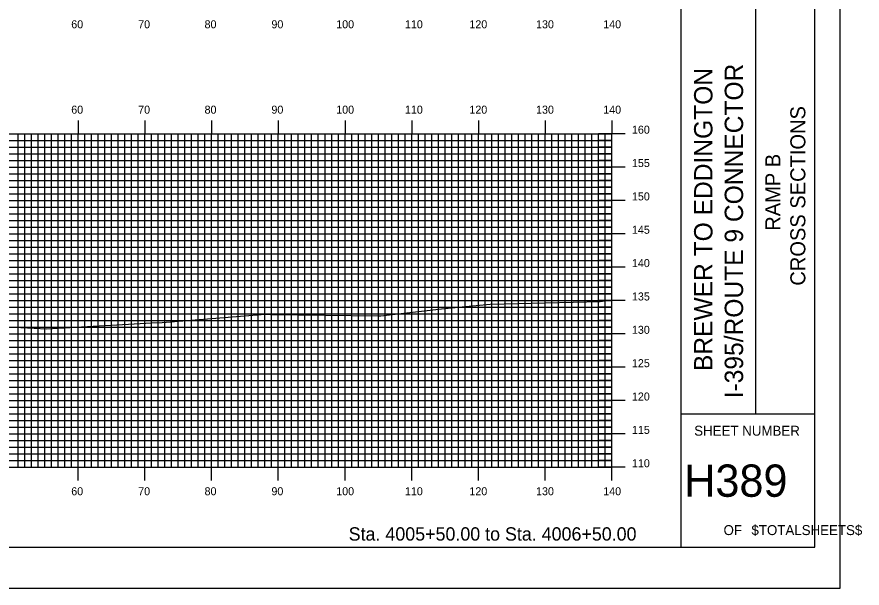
# Model space of a CAD drawing. Extents: x 851360 to 851703, y 364661 to 364881.
# Drawn here: x 851576.6 to 851703.2, y 364661.3 to 364746.9 of the extents above; entities that cross this region are included whole.
import ezdxf

# ---------------------------------------------------------------- set-up
doc = ezdxf.new("R2010")
doc.units = 0
for name, color, linetype in [('BORDER', 7, 'Continuous'), ('H_V ANNOTATION', 7, 'Continuous'), ('MAJOR', 7, 'Continuous'), ('MINOR', 7, 'Continuous'), ('PLOT BOUNDARY', 7, 'Continuous'), ('S_Roadway_Centerline', 7, 'Continuous')]:
    doc.layers.add(name, color=color, linetype=linetype)

msp = doc.modelspace()

# ---------------------------------------------------------------- linework, layer by layer
at = {"layer": 'BORDER'}
for p, q in [((851676.13, 364667.37), (851676.13, 364877.37)), ((851687.31, 364687.38), (851687.31, 364757.38)), ((851676.13, 364687.38), (851696.13, 364687.38))]:
    msp.add_line(p, q, dxfattribs=at)
msp.add_lwpolyline([(851376.13, 364667.37), (851696.13, 364667.37), (851696.13, 364877.37), (851376.13, 364877.37)], close=True, dxfattribs=at)
at = {"layer": 'MAJOR'}
for p, q in [((851585.73, 364731.37), (851585.73, 364729.37)), ((851595.73, 364731.37), (851595.73, 364729.37)), ((851605.73, 364731.37), (851605.73, 364729.37)), ((851615.73, 364731.37), (851615.73, 364729.37)), ((851625.73, 364731.37), (851625.73, 364729.37)), ((851635.73, 364731.37), (851635.73, 364729.37)), ((851645.73, 364731.37), (851645.73, 364729.37)), ((851655.73, 364731.37), (851655.73, 364729.37)), ((851665.73, 364731.37), (851665.73, 364729.37)), ((851385.73, 364729.37), (851665.73, 364729.37)), ((851385.73, 364729.37), (851665.73, 364729.37)), ((851585.73, 364679.37), (851585.73, 364729.37)), ((851595.73, 364679.37), (851595.73, 364729.37)), ((851605.73, 364679.37), (851605.73, 364729.37)), ((851615.73, 364679.37), (851615.73, 364729.37)), ((851625.73, 364679.37), (851625.73, 364729.37)), ((851635.73, 364679.37), (851635.73, 364729.37)), ((851645.73, 364679.37), (851645.73, 364729.37)), ((851655.73, 364679.37), (851655.73, 364729.37)), ((851667.73, 364729.37), (851663.72, 364729.37)), ((851665.73, 364679.37), (851665.73, 364729.37)), ((851665.73, 364679.37), (851665.73, 364729.37)), ((851385.73, 364724.37), (851665.73, 364724.37)), ((851667.73, 364724.37), (851663.72, 364724.37)), ((851385.73, 364719.37), (851665.73, 364719.37)), ((851667.73, 364719.37), (851663.72, 364719.37)), ((851385.73, 364714.37), (851665.73, 364714.37)), ((851667.73, 364714.37), (851663.72, 364714.37)), ((851385.73, 364709.37), (851665.73, 364709.37)), ((851667.73, 364709.37), (851663.72, 364709.37)), ((851385.73, 364704.37), (851665.73, 364704.37)), ((851667.73, 364704.37), (851663.72, 364704.37)), ((851385.73, 364699.37), (851665.73, 364699.37)), ((851667.73, 364699.37), (851663.72, 364699.37)), ((851385.73, 364694.37), (851665.73, 364694.37)), ((851667.73, 364694.37), (851663.72, 364694.37)), ((851385.73, 364689.37), (851665.73, 364689.37)), ((851667.73, 364689.37), (851663.72, 364689.37)), ((851385.73, 364684.37), (851665.73, 364684.37)), ((851667.73, 364684.37), (851663.72, 364684.37)), ((851385.73, 364679.37), (851665.73, 364679.37)), ((851385.73, 364679.37), (851665.73, 364679.37)), ((851585.73, 364677.37), (851585.73, 364679.37)), ((851595.73, 364677.37), (851595.73, 364679.37)), ((851605.73, 364677.37), (851605.73, 364679.37)), ((851615.73, 364677.37), (851615.73, 364679.37)), ((851625.73, 364677.37), (851625.73, 364679.37)), ((851635.73, 364677.37), (851635.73, 364679.37)), ((851645.73, 364677.37), (851645.73, 364679.37)), ((851655.73, 364677.37), (851655.73, 364679.37)), ((851667.73, 364679.37), (851663.72, 364679.37)), ((851665.73, 364677.37), (851665.73, 364679.37))]:
    msp.add_line(p, q, dxfattribs=at)
at = {"layer": 'MINOR'}
for p, q in [((851385.73, 364728.37), (851665.73, 364728.37)), ((851576.73, 364679.37), (851576.73, 364729.37)), ((851577.73, 364679.37), (851577.73, 364729.37)), ((851578.73, 364679.37), (851578.73, 364729.37)), ((851579.73, 364679.37), (851579.73, 364729.37)), ((851580.73, 364679.37), (851580.73, 364729.37)), ((851581.73, 364679.37), (851581.73, 364729.37)), ((851582.73, 364679.37), (851582.73, 364729.37)), ((851583.73, 364679.37), (851583.73, 364729.37)), ((851584.73, 364679.37), (851584.73, 364729.37)), ((851586.73, 364679.37), (851586.73, 364729.37)), ((851587.73, 364679.37), (851587.73, 364729.37)), ((851588.73, 364679.37), (851588.73, 364729.37)), ((851589.73, 364679.37), (851589.73, 364729.37)), ((851590.73, 364679.37), (851590.73, 364729.37)), ((851591.73, 364679.37), (851591.73, 364729.37)), ((851592.73, 364679.37), (851592.73, 364729.37)), ((851593.73, 364679.37), (851593.73, 364729.37)), ((851594.73, 364679.37), (851594.73, 364729.37)), ((851596.73, 364679.37), (851596.73, 364729.37)), ((851597.73, 364679.37), (851597.73, 364729.37)), ((851598.73, 364679.37), (851598.73, 364729.37)), ((851599.73, 364679.37), (851599.73, 364729.37)), ((851600.73, 364679.37), (851600.73, 364729.37)), ((851601.73, 364679.37), (851601.73, 364729.37)), ((851602.73, 364679.37), (851602.73, 364729.37)), ((851603.73, 364679.37), (851603.73, 364729.37)), ((851604.73, 364679.37), (851604.73, 364729.37)), ((851606.73, 364679.37), (851606.73, 364729.37)), ((851607.73, 364679.37), (851607.73, 364729.37)), ((851608.73, 364679.37), (851608.73, 364729.37)), ((851609.73, 364679.37), (851609.73, 364729.37)), ((851610.73, 364679.37), (851610.73, 364729.37)), ((851611.73, 364679.37), (851611.73, 364729.37)), ((851612.73, 364679.37), (851612.73, 364729.37)), ((851613.73, 364679.37), (851613.73, 364729.37)), ((851614.73, 364679.37), (851614.73, 364729.37)), ((851616.73, 364679.37), (851616.73, 364729.37)), ((851617.73, 364679.37), (851617.73, 364729.37)), ((851618.73, 364679.37), (851618.73, 364729.37)), ((851619.73, 364679.37), (851619.73, 364729.37)), ((851620.73, 364679.37), (851620.73, 364729.37)), ((851621.73, 364679.37), (851621.73, 364729.37)), ((851622.73, 364679.37), (851622.73, 364729.37)), ((851623.73, 364679.37), (851623.73, 364729.37)), ((851624.73, 364679.37), (851624.73, 364729.37)), ((851626.73, 364679.37), (851626.73, 364729.37)), ((851627.73, 364679.37), (851627.73, 364729.37)), ((851628.73, 364679.37), (851628.73, 364729.37)), ((851629.73, 364679.37), (851629.73, 364729.37)), ((851630.73, 364679.37), (851630.73, 364729.37)), ((851631.73, 364679.37), (851631.73, 364729.37)), ((851632.73, 364679.37), (851632.73, 364729.37)), ((851633.73, 364679.37), (851633.73, 364729.37)), ((851634.73, 364679.37), (851634.73, 364729.37)), ((851636.73, 364679.37), (851636.73, 364729.37)), ((851637.73, 364679.37), (851637.73, 364729.37)), ((851638.73, 364679.37), (851638.73, 364729.37)), ((851639.73, 364679.37), (851639.73, 364729.37)), ((851640.73, 364679.37), (851640.73, 364729.37)), ((851641.73, 364679.37), (851641.73, 364729.37)), ((851642.73, 364679.37), (851642.73, 364729.37)), ((851643.73, 364679.37), (851643.73, 364729.37)), ((851644.73, 364679.37), (851644.73, 364729.37)), ((851646.73, 364679.37), (851646.73, 364729.37)), ((851647.73, 364679.37), (851647.73, 364729.37)), ((851648.73, 364679.37), (851648.73, 364729.37)), ((851649.73, 364679.37), (851649.73, 364729.37)), ((851650.73, 364679.37), (851650.73, 364729.37)), ((851651.73, 364679.37), (851651.73, 364729.37)), ((851652.73, 364679.37), (851652.73, 364729.37)), ((851653.73, 364679.37), (851653.73, 364729.37)), ((851654.73, 364679.37), (851654.73, 364729.37)), ((851656.73, 364679.37), (851656.73, 364729.37)), ((851657.73, 364679.37), (851657.73, 364729.37)), ((851658.73, 364679.37), (851658.73, 364729.37)), ((851659.73, 364679.37), (851659.73, 364729.37)), ((851660.73, 364679.37), (851660.73, 364729.37)), ((851661.73, 364679.37), (851661.73, 364729.37)), ((851662.73, 364679.37), (851662.73, 364729.37)), ((851665.73, 364728.37), (851663.72, 364728.37)), ((851663.73, 364679.37), (851663.73, 364729.37)), ((851664.73, 364679.37), (851664.73, 364729.37)), ((851385.73, 364727.37), (851665.73, 364727.37)), ((851665.73, 364727.37), (851663.72, 364727.37)), ((851385.73, 364726.37), (851665.73, 364726.37)), ((851665.73, 364726.37), (851663.72, 364726.37)), ((851385.73, 364725.37), (851665.73, 364725.37)), ((851665.73, 364725.37), (851663.72, 364725.37)), ((851385.73, 364723.37), (851665.73, 364723.37)), ((851665.73, 364723.37), (851663.72, 364723.37)), ((851385.73, 364722.37), (851665.73, 364722.37)), ((851665.73, 364722.37), (851663.72, 364722.37)), ((851385.73, 364721.37), (851665.73, 364721.37)), ((851665.73, 364721.37), (851663.72, 364721.37)), ((851385.73, 364720.37), (851665.73, 364720.37)), ((851665.73, 364720.37), (851663.72, 364720.37)), ((851385.73, 364718.37), (851665.73, 364718.37)), ((851665.73, 364718.37), (851663.72, 364718.37)), ((851385.73, 364717.37), (851665.73, 364717.37)), ((851665.73, 364717.37), (851663.72, 364717.37)), ((851385.73, 364716.37), (851665.73, 364716.37)), ((851665.73, 364716.37), (851663.72, 364716.37)), ((851385.73, 364715.37), (851665.73, 364715.37)), ((851665.73, 364715.37), (851663.72, 364715.37)), ((851385.73, 364713.37), (851665.73, 364713.37)), ((851665.73, 364713.37), (851663.72, 364713.37)), ((851385.73, 364712.37), (851665.73, 364712.37)), ((851665.73, 364712.37), (851663.72, 364712.37)), ((851385.73, 364711.37), (851665.73, 364711.37)), ((851665.73, 364711.37), (851663.72, 364711.37)), ((851385.73, 364710.37), (851665.73, 364710.37)), ((851665.73, 364710.37), (851663.72, 364710.37)), ((851385.73, 364708.37), (851665.73, 364708.37)), ((851665.73, 364708.37), (851663.72, 364708.37)), ((851385.73, 364707.37), (851665.73, 364707.37)), ((851665.73, 364707.37), (851663.72, 364707.37)), ((851385.73, 364706.37), (851665.73, 364706.37)), ((851665.73, 364706.37), (851663.72, 364706.37)), ((851385.73, 364705.37), (851665.73, 364705.37)), ((851665.73, 364705.37), (851663.72, 364705.37)), ((851385.73, 364703.37), (851665.73, 364703.37)), ((851665.73, 364703.37), (851663.72, 364703.37)), ((851385.73, 364702.37), (851665.73, 364702.37)), ((851665.73, 364702.37), (851663.72, 364702.37)), ((851385.73, 364701.37), (851665.73, 364701.37)), ((851385.73, 364700.37), (851665.73, 364700.37)), ((851665.73, 364701.37), (851663.72, 364701.37)), ((851665.73, 364700.37), (851663.72, 364700.37)), ((851385.73, 364698.37), (851665.73, 364698.37)), ((851665.73, 364698.37), (851663.72, 364698.37)), ((851385.73, 364697.37), (851665.73, 364697.37)), ((851665.73, 364697.37), (851663.72, 364697.37)), ((851385.73, 364696.37), (851665.73, 364696.37)), ((851385.73, 364695.37), (851665.73, 364695.37)), ((851665.73, 364696.37), (851663.72, 364696.37)), ((851665.73, 364695.37), (851663.72, 364695.37)), ((851385.73, 364693.37), (851665.73, 364693.37)), ((851665.73, 364693.37), (851663.72, 364693.37)), ((851385.73, 364692.37), (851665.73, 364692.37)), ((851665.73, 364692.37), (851663.72, 364692.37)), ((851385.73, 364691.37), (851665.73, 364691.37)), ((851385.73, 364690.37), (851665.73, 364690.37)), ((851665.73, 364691.37), (851663.72, 364691.37)), ((851665.73, 364690.37), (851663.72, 364690.37)), ((851385.73, 364688.37), (851665.73, 364688.37)), ((851665.73, 364688.37), (851663.72, 364688.37)), ((851385.73, 364687.37), (851665.73, 364687.37)), ((851665.73, 364687.37), (851663.72, 364687.37)), ((851385.73, 364686.37), (851665.73, 364686.37)), ((851385.73, 364685.37), (851665.73, 364685.37)), ((851665.73, 364686.37), (851663.72, 364686.37)), ((851665.73, 364685.37), (851663.72, 364685.37)), ((851385.73, 364683.37), (851665.73, 364683.37)), ((851665.73, 364683.37), (851663.72, 364683.37)), ((851385.73, 364682.37), (851665.73, 364682.37)), ((851385.73, 364681.37), (851665.73, 364681.37)), ((851665.73, 364682.37), (851663.72, 364682.37)), ((851665.73, 364681.37), (851663.72, 364681.37)), ((851385.73, 364680.37), (851665.73, 364680.37)), ((851665.73, 364680.37), (851663.72, 364680.37))]:
    msp.add_line(p, q, dxfattribs=at)
at = {"layer": 'PLOT BOUNDARY'}
msp.add_lwpolyline([(851359.94, 364661.25), (851699.94, 364661.25), (851699.94, 364881.25), (851359.94, 364881.25)], close=True, dxfattribs=at)
at = {"layer": 'S_Roadway_Centerline'}
msp.add_lwpolyline([(851567.97, 364701.34), (851569.96, 364700.89), (851573.14, 364700.5), (851579.13, 364700.2), (851581, 364700.11), (851596.8, 364701.03), (851598.31, 364701.08), (851613.16, 364702.25), (851613.88, 364702.3), (851614.56, 364702.29), (851630.83, 364702.08), (851631.08, 364702.08), (851640.65, 364703.15), (851647.46, 364703.83), (851659.92, 364704.09), (851663.96, 364704.22), (851665.73, 364704.47)], dxfattribs=at)

# ---------------------------------------------------------------- texts
at = {"layer": 'BORDER'}
for s, height, p in [('I-395/ROUTE 9 CONNECTOR', 2.7557, (851685.39, 364689.7)), ('BREWER TO EDDINGTON', 2.7557, (851680.8, 364693.78)), ('CROSS SECTIONS', 2.25, (851694.72, 364706.59)), ('RAMP B', 2.25, (851690.97, 364714.82))]:
    msp.add_text(s, height=height, rotation=90, dxfattribs=at).set_placement(p)
for s, height, p in [('SHEET NUMBER', 1.4905, (851678.06, 364684.1)), ('H389', 4.839, (851676.57, 364674.94)), ('OF', 1.491, (851682.46, 364669.2)), ('$TOTALSHEETS$', 1.4905, (851686.64, 364669.2))]:
    msp.add_text(s, height=height, dxfattribs=at).set_placement(p)
at = {"layer": 'H_V ANNOTATION'}
for s, height, p in [('60', 1.2, (851584.7, 364745.17)), ('70', 1.2, (851594.73, 364745.17)), ('80', 1.2, (851604.68, 364745.17)), ('90', 1.2, (851614.7, 364745.17)), ('100', 1.2, (851624.41, 364745.17)), ('110', 1.2, (851634.71, 364745.17)), ('120', 1.2, (851644.37, 364745.17)), ('130', 1.2, (851654.36, 364745.17)), ('140', 1.2, (851664.43, 364745.17)), ('60', 1.2, (851584.7, 364732.37)), ('70', 1.2, (851594.73, 364732.37)), ('80', 1.2, (851604.68, 364732.37)), ('90', 1.2, (851614.7, 364732.37)), ('100', 1.2, (851624.41, 364732.37)), ('110', 1.2, (851634.71, 364732.37)), ('120', 1.2, (851644.37, 364732.37)), ('130', 1.2, (851654.36, 364732.37)), ('140', 1.2, (851664.43, 364732.37)), ('160', 1.2, (851668.73, 364729.37)), ('155', 1.2, (851668.73, 364724.37)), ('150', 1.2, (851668.73, 364719.37)), ('145', 1.2, (851668.73, 364714.37)), ('140', 1.2, (851668.73, 364709.37)), ('135', 1.2, (851668.73, 364704.37)), ('130', 1.2, (851668.73, 364699.37)), ('125', 1.2, (851668.73, 364694.37)), ('120', 1.2, (851668.73, 364689.37)), ('115', 1.2, (851668.73, 364684.37)), ('110', 1.2, (851668.73, 364679.37)), ('60', 1.2, (851584.7, 364675.17)), ('70', 1.2, (851594.73, 364675.17)), ('80', 1.2, (851604.68, 364675.17)), ('90', 1.2, (851614.7, 364675.17)), ('100', 1.2, (851624.41, 364675.17)), ('110', 1.2, (851634.71, 364675.17)), ('120', 1.2, (851644.37, 364675.17)), ('130', 1.2, (851654.36, 364675.17)), ('140', 1.2, (851664.43, 364675.17)), ('Sta. 4005+50.00 to Sta. 4006+50.00', 2.0004, (851626.28, 364668.37))]:
    msp.add_text(s, height=height, dxfattribs=at).set_placement(p)

doc.saveas('drawing.dxf')
